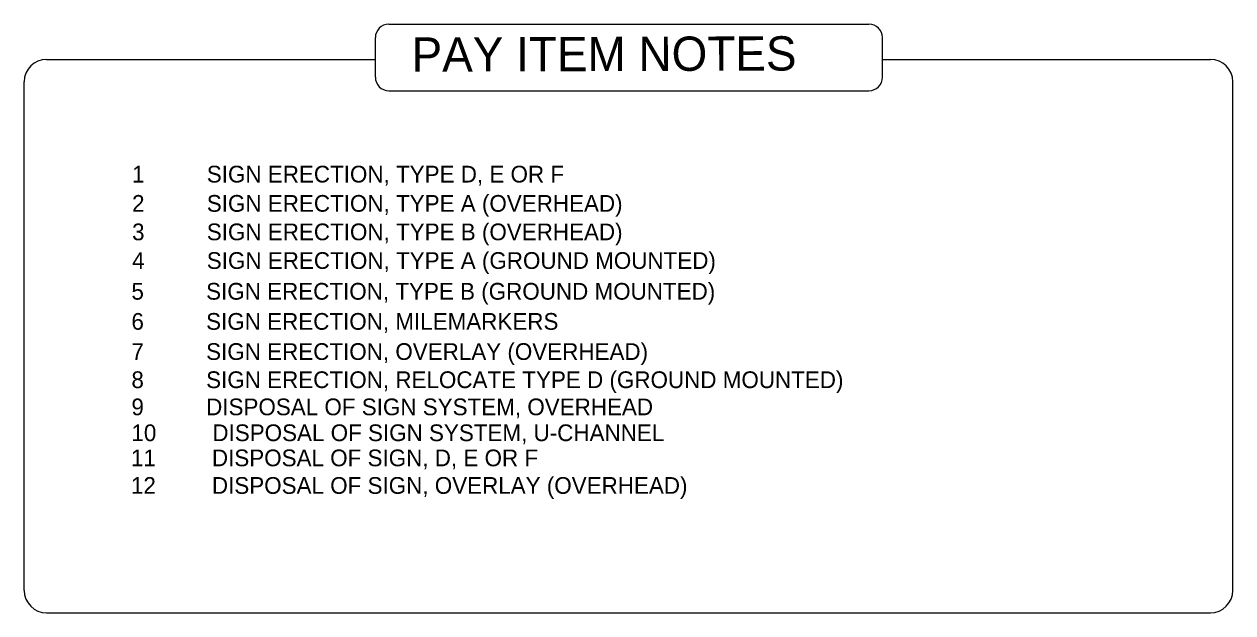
# Model space of a CAD drawing. Extents: x 49201 to 52602, y 49383 to 50479.
# Drawn here: x 49201.3 to 49689.7, y 49646.5 to 49884.7 of the extents above; entities that cross this region are included whole.
import ezdxf

# ---------------------------------------------------------------- set-up
doc = ezdxf.new("R2010")
doc.units = 0
doc.layers.add('Default', color=7, linetype='Continuous')
doc.layers.add('Sheet Title CELL', color=7, linetype='Continuous')

msp = doc.modelspace()

# ---------------------------------------------------------------- linework, layer by layer
at = {"layer": 'Sheet Title CELL'}
for p, q in [((49343.19, 49863.21), (49343.19, 49879.23)), ((49548.12, 49863.21), (49548.12, 49879.23)), ((49210.34, 49870.43), (49343.19, 49870.43)), ((49548.12, 49870.43), (49680.63, 49870.43)), ((49201.26, 49655.56), (49201.26, 49861.34)), ((49689.72, 49655.56), (49689.72, 49861.34)), ((49210.34, 49646.48), (49680.63, 49646.48))]:
    msp.add_line(p, q, dxfattribs=at)
for points in [[(49348.64, 49884.69), (49542.66, 49884.69)], [(49348.64, 49857.76), (49542.66, 49857.76)]]:
    msp.add_lwpolyline(points, dxfattribs=at)
for centre, radius, start, end in [((49348.64, 49879.23), 5.45, 90, 180), ((49542.66, 49879.23), 5.45, 0, 90), ((49210.34, 49861.34), 9.09, 90, 180), ((49680.63, 49861.34), 9.09, 0, 90), ((49348.64, 49863.21), 5.45, 180, 270), ((49542.66, 49863.21), 5.45, 270, 0), ((49210.34, 49655.56), 9.09, 180, 270), ((49680.63, 49655.56), 9.09, 270, 0)]:
    msp.add_arc(centre, radius, start, end, dxfattribs=at)

# ---------------------------------------------------------------- texts
at = {"layer": 'Default'}
msp.add_text('PAY ITEM NOTES', height=13.8661, rotation=0.1822, dxfattribs=at).set_placement((49357.84, 49865.43))
for s, p in [('1          SIGN ERECTION, TYPE D, E OR F', (49244.87, 49820.61)), ('2          SIGN ERECTION, TYPE A (OVERHEAD)', (49244.87, 49808.77)), ('3          SIGN ERECTION, TYPE B (OVERHEAD)', (49244.87, 49797.24)), ('4          SIGN ERECTION, TYPE A (GROUND MOUNTED)', (49244.87, 49785.65)), ('5          SIGN ERECTION, TYPE B (GROUND MOUNTED)', (49244.6, 49773.2)), ('6          SIGN ERECTION, MILEMARKERS', (49244.6, 49761.02)), ('7          SIGN ERECTION, OVERLAY (OVERHEAD)', (49244.6, 49748.82)), ('8          SIGN ERECTION, RELOCATE TYPE D (GROUND MOUNTED)', (49244.6, 49737.42)), ('9          DISPOSAL OF SIGN SYSTEM, OVERHEAD', (49244.6, 49726.43)), ('10         DISPOSAL OF SIGN SYSTEM, U-CHANNEL', (49244.6, 49715.96)), ('11         DISPOSAL OF SIGN, D, E OR F', (49244.42, 49705.79)), ('12         DISPOSAL OF SIGN, OVERLAY (OVERHEAD)', (49244.42, 49694.64))]:
    msp.add_text(s, height=6.7709, dxfattribs=at).set_placement(p)

doc.saveas('drawing.dxf')
